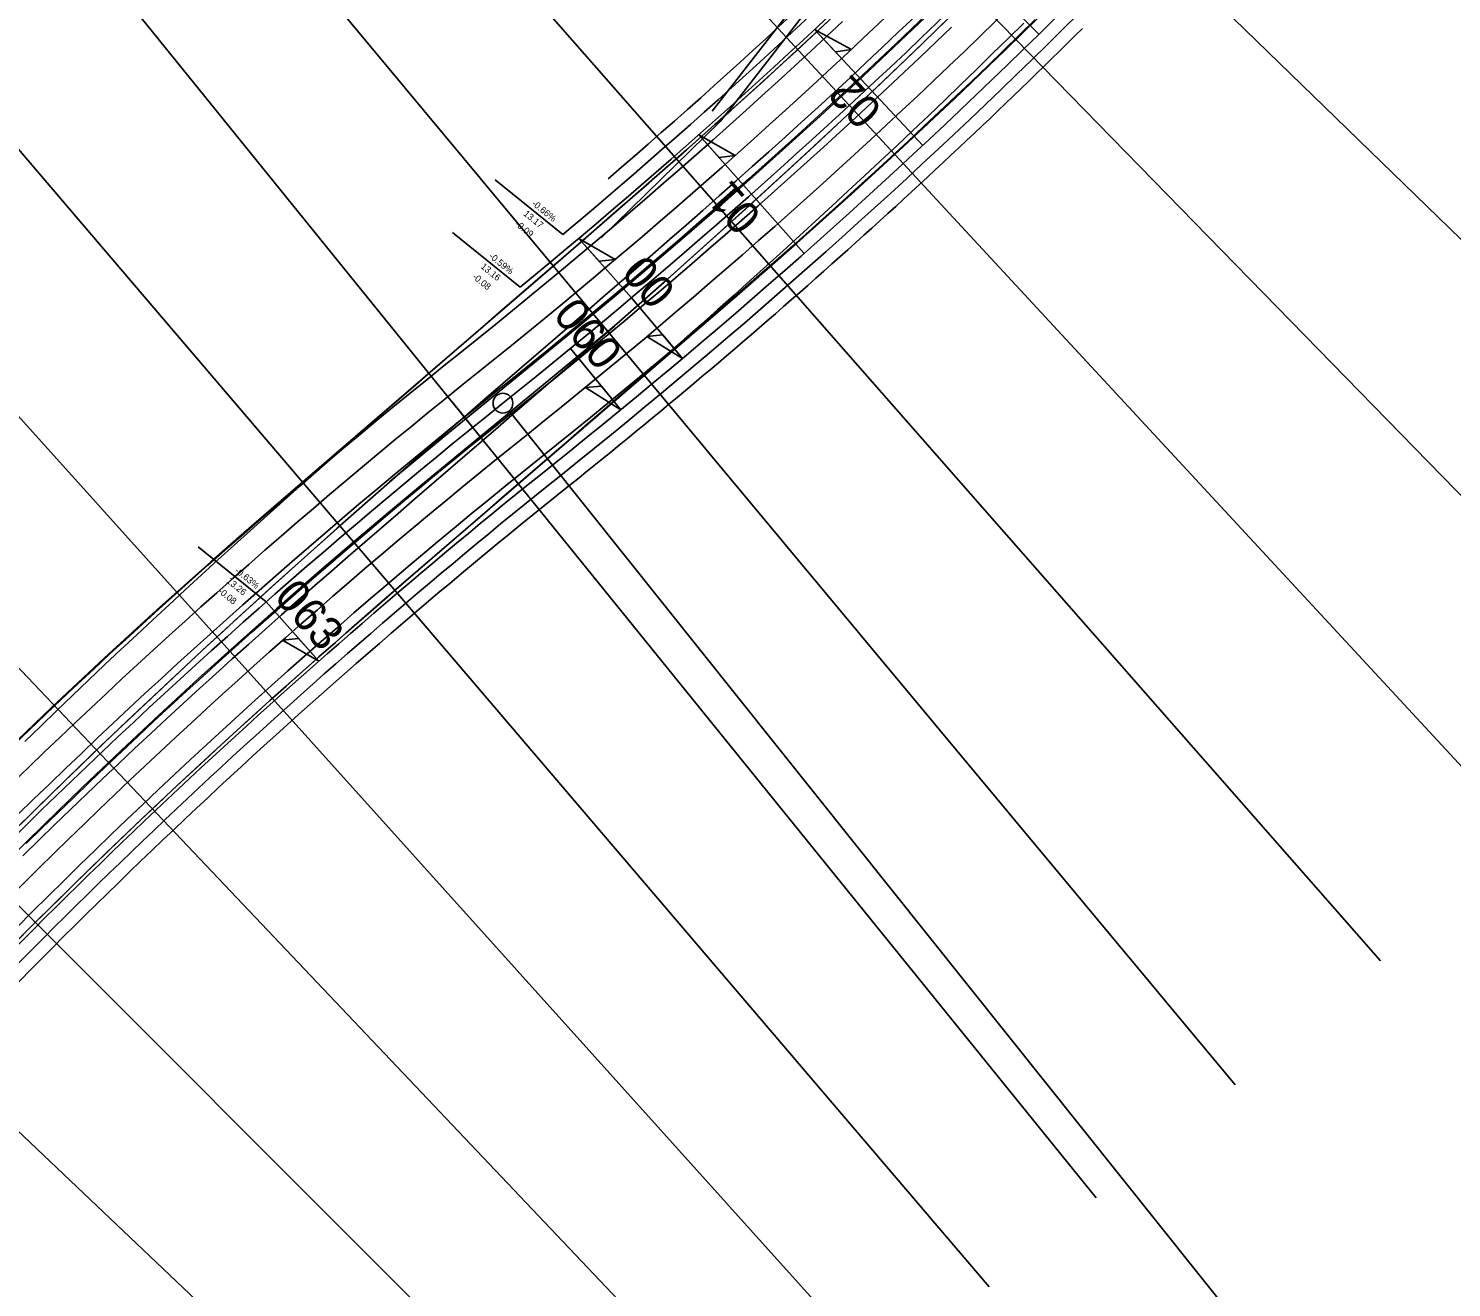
# Model space of a CAD drawing. Extents: x 2293233 to 2294507, y 892788 to 894229.
# Drawn here: x 2293544.7 to 2293760.1, y 893049.3 to 893239.9 of the extents above; entities that cross this region are included whole.
import ezdxf

# ---------------------------------------------------------------- set-up
doc = ezdxf.new("R2010")
doc.units = 0
for name, color, linetype in [('COGO Default Curve', 7, 'Continuous'), ('Default', 7, 'Continuous'), ('Prop EOT', 7, 'Continuous'), ('Prop Horizontal Alignment', 7, 'Continuous'), ('Prop Paved Shoulder', 7, 'Continuous'), ('Prop Superelevation  Arrow CELL', 7, 'Continuous'), ('Prop Superelevation Label', 7, 'Continuous'), ('Scratch_Level_0', 7, 'Continuous'), ('Scratch_Level_4', 7, 'Continuous'), ('Scratch_Level_5', 7, 'Continuous'), ('Scratch_Level_6', 7, 'Continuous')]:
    doc.layers.add(name, color=color, linetype=linetype)

msp = doc.modelspace()

# ---------------------------------------------------------------- linework, layer by layer
at = {"layer": 'COGO Default Curve'}
for points in [[(2293540.51, 893129.71), (2293548.21, 893137.09), (2293556.25, 893144.61), (2293564.12, 893151.82), (2293572.32, 893159.16), (2293576.58, 893162.91), (2293581.11, 893166.85), (2293623.72, 893203.59), (2293633.79, 893212.3), (2293644.32, 893221.52), (2293653.27, 893229.52), (2293658.2, 893234.01), (2293663.1, 893238.53), (2293667.97, 893243.08)], [(2293683.19, 893244.24), (2293678.63, 893239.85), (2293673.79, 893235.26), (2293669.17, 893230.93), (2293664.52, 893226.64), (2293659.84, 893222.37), (2293654.88, 893217.92), (2293649.64, 893213.27), (2293644.36, 893208.67), (2293639.05, 893204.11), (2293633.96, 893199.79), (2293626.26, 893193.39), (2293607.66, 893178.13), (2293599.45, 893171.3), (2293593.21, 893165.79), (2293587.49, 893160.7), (2293581.8, 893155.58), (2293576.38, 893150.65), (2293570.99, 893145.69), (2293565.87, 893140.92), (2293560.78, 893136.12), (2293555.72, 893131.29), (2293550.68, 893126.43), (2293545.92, 893121.77), (2293541.18, 893117.08)], [(2293541.47, 893113.86), (2293547.17, 893119.47), (2293552.91, 893125.04), (2293558.71, 893130.55), (2293564.55, 893136.01), (2293570.43, 893141.43), (2293576.36, 893146.79), (2293582.34, 893152.11), (2293588.37, 893157.38), (2293594.44, 893162.59), (2293599.53, 893166.9), (2293604.66, 893171.18), (2293623.51, 893186.65), (2293632.76, 893194.33), (2293633.78, 893195.19), (2293641.01, 893201.57), (2293647.96, 893207.78), (2293654.87, 893214.04), (2293661.49, 893220.12), (2293667.83, 893226.02), (2293674.13, 893231.97), (2293680.14, 893237.74), (2293686.34, 893243.78)], [(2293697.59, 893241.55), (2293692.58, 893236.66), (2293684.87, 893229.27), (2293677.09, 893221.97), (2293669.22, 893214.76), (2293661.01, 893207.41), (2293656.51, 893203.45), (2293651.97, 893199.5), (2293609.11, 893162.55), (2293598.54, 893153.4), (2293592.76, 893148.36), (2293587.51, 893143.73), (2293582.78, 893139.51), (2293578.08, 893135.27), (2293572.67, 893130.32), (2293567.29, 893125.33), (2293561.96, 893120.3), (2293556.42, 893114.99), (2293551.16, 893109.88), (2293545.7, 893104.49), (2293540.52, 893099.3)], [(2293667.93, 893240.97), (2293665.51, 893238.7), (2293663.08, 893236.44), (2293660.64, 893234.19), (2293658.2, 893231.94), (2293655.74, 893229.7), (2293653.28, 893227.48), (2293650.81, 893225.26), (2293648.33, 893223.05), (2293645.85, 893220.84), (2293643.36, 893218.65), (2293640.85, 893216.47), (2293638.35, 893214.29), (2293635.83, 893212.12), (2293633.31, 893209.97), (2293630.77, 893207.82), (2293628.24, 893205.68), (2293625.69, 893203.55), (2293623.13, 893201.43), (2293620.57, 893199.31), (2293618, 893197.21), (2293615.43, 893195.11), (2293612.84, 893193.03), (2293610.25, 893190.95), (2293607.66, 893188.87), (2293605.06, 893186.78), (2293602.48, 893184.68), (2293599.9, 893182.57), (2293597.32, 893180.44), (2293594.76, 893178.31), (2293592.19, 893176.17), (2293589.64, 893174.02), (2293587.09, 893171.86), (2293584.55, 893169.68), (2293582.02, 893167.5), (2293579.49, 893165.31), (2293576.97, 893163.12), (2293574.46, 893160.91), (2293571.95, 893158.69), (2293569.45, 893156.47), (2293566.96, 893154.23), (2293564.48, 893151.99), (2293562.01, 893149.74), (2293559.54, 893147.48), (2293557.08, 893145.21), (2293554.63, 893142.93), (2293552.19, 893140.64), (2293549.75, 893138.35), (2293547.32, 893136.05), (2293544.9, 893133.73), (2293542.49, 893131.41)], [(2293542.82, 893101.61), (2293545.16, 893103.96), (2293547.52, 893106.29), (2293549.88, 893108.62), (2293552.24, 893110.94), (2293554.62, 893113.25), (2293557, 893115.56), (2293559.39, 893117.85), (2293561.79, 893120.14), (2293564.2, 893122.42), (2293566.61, 893124.69), (2293569.04, 893126.96), (2293571.47, 893129.21), (2293573.9, 893131.46), (2293576.35, 893133.7), (2293578.8, 893135.92), (2293581.26, 893138.15), (2293583.73, 893140.36), (2293586.21, 893142.57), (2293588.7, 893144.77), (2293591.19, 893146.97), (2293593.68, 893149.16), (2293596.19, 893151.35), (2293598.69, 893153.53), (2293601.21, 893155.72), (2293603.72, 893157.9), (2293606.24, 893160.07), (2293608.76, 893162.25), (2293611.28, 893164.43), (2293613.81, 893166.6), (2293616.33, 893168.78), (2293618.86, 893170.96), (2293621.38, 893173.14), (2293623.91, 893175.32), (2293626.43, 893177.5), (2293628.95, 893179.69), (2293631.47, 893181.88), (2293633.99, 893184.07), (2293636.5, 893186.27), (2293639.01, 893188.47), (2293641.52, 893190.67), (2293644.02, 893192.88), (2293646.52, 893195.1), (2293649.02, 893197.32), (2293651.51, 893199.55), (2293653.99, 893201.78), (2293656.48, 893204.02), (2293658.95, 893206.26), (2293661.42, 893208.51), (2293663.89, 893210.77), (2293666.35, 893213.03), (2293668.8, 893215.3), (2293671.25, 893217.58), (2293673.69, 893219.86), (2293676.12, 893222.15), (2293678.55, 893224.45), (2293680.97, 893226.75), (2293683.39, 893229.06), (2293685.79, 893231.38), (2293688.2, 893233.71), (2293690.59, 893236.04), (2293692.98, 893238.38), (2293695.36, 893240.73)], [(2293543.03, 893103.87), (2293545.38, 893106.22), (2293547.73, 893108.56), (2293550.09, 893110.89), (2293552.46, 893113.22), (2293554.84, 893115.53), (2293557.23, 893117.84), (2293559.62, 893120.14), (2293562.03, 893122.43), (2293564.44, 893124.71), (2293566.86, 893126.99), (2293569.28, 893129.25), (2293571.72, 893131.51), (2293574.16, 893133.75), (2293576.61, 893135.99), (2293579.07, 893138.22), (2293581.54, 893140.44), (2293584.01, 893142.66), (2293586.5, 893144.86), (2293588.99, 893147.06), (2293591.49, 893149.24), (2293593.99, 893151.42), (2293596.5, 893153.59), (2293599.03, 893155.75), (2293601.55, 893157.9), (2293604.09, 893160.04), (2293606.63, 893162.18), (2293609.19, 893164.3), (2293611.74, 893166.41), (2293614.31, 893168.52), (2293616.88, 893170.62), (2293619.47, 893172.7), (2293622.05, 893174.78), (2293624.65, 893176.86), (2293627.24, 893178.95), (2293629.83, 893181.05), (2293632.41, 893183.16), (2293634.99, 893185.28), (2293637.56, 893187.41), (2293640.13, 893189.55), (2293642.68, 893191.7), (2293645.24, 893193.86), (2293647.78, 893196.03), (2293650.32, 893198.21), (2293652.85, 893200.39), (2293655.37, 893202.59), (2293657.89, 893204.8), (2293660.39, 893207.01), (2293662.89, 893209.23), (2293665.39, 893211.47), (2293667.87, 893213.71), (2293670.35, 893215.96), (2293672.82, 893218.21), (2293675.28, 893220.48), (2293677.74, 893222.76), (2293680.18, 893225.04), (2293682.62, 893227.34), (2293685.05, 893229.64), (2293687.47, 893231.95), (2293689.89, 893234.27), (2293692.29, 893236.59), (2293694.69, 893238.93), (2293697.08, 893241.27)], [(2293678.85, 893241.67), (2293676.42, 893239.37), (2293673.99, 893237.07), (2293671.55, 893234.78), (2293669.11, 893232.5), (2293666.65, 893230.23), (2293664.19, 893227.96), (2293661.72, 893225.71), (2293659.25, 893223.46), (2293656.76, 893221.23), (2293654.27, 893219), (2293651.77, 893216.77), (2293649.27, 893214.56), (2293646.77, 893212.35), (2293644.25, 893210.15), (2293641.74, 893207.95), (2293639.22, 893205.76), (2293636.7, 893203.57), (2293634.18, 893201.39), (2293631.65, 893199.21), (2293629.13, 893197.03), (2293626.6, 893194.85), (2293624.08, 893192.68), (2293621.56, 893190.5), (2293619.04, 893188.32), (2293616.52, 893186.15), (2293614, 893183.97), (2293611.48, 893181.79), (2293608.97, 893179.61), (2293606.46, 893177.43), (2293603.95, 893175.24), (2293601.45, 893173.05), (2293598.95, 893170.86), (2293596.46, 893168.67), (2293593.97, 893166.46), (2293591.48, 893164.26), (2293589, 893162.05), (2293586.53, 893159.83), (2293584.06, 893157.61), (2293581.59, 893155.39), (2293579.14, 893153.16), (2293576.68, 893150.92), (2293574.24, 893148.68), (2293571.8, 893146.43), (2293569.36, 893144.17), (2293566.93, 893141.91), (2293564.51, 893139.64), (2293562.1, 893137.37), (2293559.69, 893135.09), (2293557.29, 893132.8), (2293554.9, 893130.5), (2293552.51, 893128.2), (2293550.13, 893125.89), (2293547.76, 893123.57), (2293545.39, 893121.25), (2293543.04, 893118.92)], [(2293680.79, 893242.16), (2293678.37, 893239.85), (2293675.94, 893237.54), (2293673.51, 893235.24), (2293671.07, 893232.95), (2293668.62, 893230.66), (2293666.16, 893228.39), (2293663.69, 893226.13), (2293661.22, 893223.87), (2293658.73, 893221.62), (2293656.24, 893219.38), (2293653.74, 893217.15), (2293651.24, 893214.93), (2293648.72, 893212.72), (2293646.2, 893210.52), (2293643.67, 893208.32), (2293641.14, 893206.14), (2293638.59, 893203.96), (2293636.04, 893201.79), (2293633.48, 893199.64), (2293630.91, 893197.49), (2293628.33, 893195.35), (2293625.75, 893193.22), (2293623.16, 893191.09), (2293620.56, 893188.98), (2293617.96, 893186.88), (2293615.34, 893184.78), (2293612.74, 893182.69), (2293610.14, 893180.6), (2293607.56, 893178.5), (2293604.98, 893176.39), (2293602.41, 893174.27), (2293599.85, 893172.14), (2293597.3, 893170.01), (2293594.76, 893167.87), (2293592.22, 893165.72), (2293589.7, 893163.56), (2293587.18, 893161.39), (2293584.67, 893159.22), (2293582.16, 893157.03), (2293579.67, 893154.84), (2293577.18, 893152.64), (2293574.7, 893150.43), (2293572.23, 893148.21), (2293569.77, 893145.99), (2293567.31, 893143.75), (2293564.87, 893141.51), (2293562.43, 893139.26), (2293560, 893137), (2293557.57, 893134.73), (2293555.16, 893132.45), (2293552.75, 893130.17), (2293550.35, 893127.88), (2293547.96, 893125.57), (2293545.58, 893123.26), (2293543.2, 893120.95)], [(2293543.92, 893114.68), (2293546.3, 893117.02), (2293548.7, 893119.35), (2293551.1, 893121.68), (2293553.52, 893123.99), (2293555.94, 893126.3), (2293558.36, 893128.6), (2293560.8, 893130.89), (2293563.24, 893133.18), (2293565.69, 893135.45), (2293568.15, 893137.72), (2293570.62, 893139.97), (2293573.1, 893142.22), (2293575.58, 893144.46), (2293578.07, 893146.7), (2293580.56, 893148.92), (2293583.06, 893151.14), (2293585.57, 893153.35), (2293588.08, 893155.56), (2293590.6, 893157.75), (2293593.11, 893159.95), (2293595.64, 893162.14), (2293598.16, 893164.32), (2293600.68, 893166.5), (2293603.21, 893168.68), (2293605.73, 893170.86), (2293608.26, 893173.04), (2293610.78, 893175.22), (2293613.31, 893177.39), (2293615.83, 893179.57), (2293618.35, 893181.75), (2293620.86, 893183.92), (2293623.38, 893186.11), (2293625.89, 893188.29), (2293628.4, 893190.47), (2293630.9, 893192.66), (2293633.4, 893194.86), (2293635.9, 893197.05), (2293638.39, 893199.25), (2293640.88, 893201.46), (2293643.36, 893203.66), (2293645.84, 893205.88), (2293648.31, 893208.1), (2293650.78, 893210.32), (2293653.24, 893212.55), (2293655.69, 893214.79), (2293658.14, 893217.03), (2293660.58, 893219.28), (2293663.02, 893221.53), (2293665.45, 893223.79), (2293667.87, 893226.06), (2293670.29, 893228.33), (2293672.7, 893230.61), (2293675.1, 893232.9), (2293677.5, 893235.2), (2293679.89, 893237.5), (2293682.27, 893239.81), (2293684.65, 893242.12)], [(2293665.75, 893240.99), (2293663.32, 893238.73), (2293660.89, 893236.47), (2293658.45, 893234.23), (2293656, 893231.99), (2293653.54, 893229.77), (2293651.08, 893227.55), (2293648.61, 893225.34), (2293646.13, 893223.13), (2293643.65, 893220.93), (2293641.15, 893218.74), (2293638.66, 893216.54), (2293636.15, 893214.36), (2293633.64, 893212.18), (2293631.13, 893210), (2293628.62, 893207.82), (2293626.1, 893205.64), (2293623.58, 893203.46), (2293621.05, 893201.29), (2293618.53, 893199.11), (2293616.01, 893196.94), (2293613.48, 893194.76), (2293610.96, 893192.58), (2293608.44, 893190.4), (2293605.91, 893188.22), (2293603.39, 893186.03), (2293600.88, 893183.84), (2293598.36, 893181.65), (2293595.85, 893179.45), (2293593.34, 893177.25), (2293590.83, 893175.04), (2293588.33, 893172.83), (2293585.83, 893170.61), (2293583.34, 893168.39), (2293580.85, 893166.16), (2293578.37, 893163.93), (2293575.89, 893161.69), (2293573.42, 893159.45), (2293570.95, 893157.19), (2293568.48, 893154.94), (2293566.03, 893152.67), (2293563.58, 893150.4), (2293561.13, 893148.12), (2293558.69, 893145.84), (2293556.26, 893143.55), (2293553.84, 893141.25), (2293551.42, 893138.94), (2293549.01, 893136.63), (2293546.6, 893134.31), (2293544.2, 893131.98)], [(2293544.39, 893116.51), (2293546.78, 893118.85), (2293549.18, 893121.19), (2293551.59, 893123.51), (2293554, 893125.83), (2293556.42, 893128.14), (2293558.86, 893130.44), (2293561.3, 893132.74), (2293563.74, 893135.02), (2293566.2, 893137.3), (2293568.66, 893139.56), (2293571.13, 893141.82), (2293573.61, 893144.07), (2293576.1, 893146.31), (2293578.6, 893148.54), (2293581.1, 893150.77), (2293583.61, 893152.98), (2293586.13, 893155.19), (2293588.66, 893157.38), (2293591.19, 893159.57), (2293593.73, 893161.75), (2293596.28, 893163.92), (2293598.84, 893166.08), (2293601.41, 893168.23), (2293603.98, 893170.37), (2293606.56, 893172.51), (2293609.15, 893174.63), (2293611.74, 893176.75), (2293614.35, 893178.85), (2293616.96, 893180.95), (2293619.57, 893183.04), (2293622.16, 893185.13), (2293624.75, 893187.23), (2293627.34, 893189.34), (2293629.91, 893191.46), (2293632.47, 893193.58), (2293635.02, 893195.71), (2293637.57, 893197.85), (2293640.11, 893200), (2293642.64, 893202.16), (2293645.16, 893204.32), (2293647.67, 893206.5), (2293650.18, 893208.68), (2293652.68, 893210.87), (2293655.17, 893213.07), (2293657.65, 893215.27), (2293660.12, 893217.49), (2293662.59, 893219.71), (2293665.05, 893221.95), (2293667.5, 893224.19), (2293669.94, 893226.44), (2293672.37, 893228.7), (2293674.8, 893230.96), (2293677.22, 893233.24), (2293679.63, 893235.52), (2293682.03, 893237.81), (2293684.43, 893240.11)]]:
    msp.add_lwpolyline(points, dxfattribs=at)
msp.add_circle((2293612.8, 893187.87), 0.0417, dxfattribs=at)
msp.add_circle((2293612.8, 893187.87), 0.0417, dxfattribs=at)
for centre, radius, start, end in [((2293023.75, 893925.54), 944, 308.6085, 321.09608), ((2293023.75, 893925.54), 956, 308.6085, 321.09608), ((2294209.34, 892440.82), 956, 128.6085, 141.01247), ((2294209.34, 892440.82), 944, 128.6085, 141.01247)]:
    msp.add_arc(centre, radius, start, end, dxfattribs=at)
at = {"layer": 'Default'}
for p, q in [((2293615.39, 893217), (2293625.63, 893208.71)), ((2293608.92, 893209.01), (2293619.15, 893200.73)), ((2293570.42, 893161.44), (2293580.72, 893153.1))]:
    msp.add_line(p, q, dxfattribs=at)
at = {"layer": 'Prop EOT'}
for centre, radius, start, end in [((2293023.75, 893925.54), 938, 309.40221, 321.09608), ((2293023.75, 893925.54), 962, 308.6085, 321.09608), ((2294209.34, 892440.82), 938, 128.6085, 137.75907)]:
    msp.add_arc(centre, radius, start, end, dxfattribs=at)
at = {"layer": 'Prop Horizontal Alignment'}
for p, q in [((2293611.98, 893179.52), (2293608.84, 893183.4)), ((2293617.48, 893182.01), (2293788.14, 892968.29))]:
    msp.add_line(p, q, dxfattribs=at)
msp.add_circle((2293616.54, 893183.18), 1.5, dxfattribs=at)
for centre, start, end in [((2293023.75, 893925.54), 308.6085, 321.09608), ((2293023.75, 893925.54), 308.6085, 321.09608), ((2294209.34, 892440.82), 128.6085, 141.01247), ((2294209.34, 892440.82), 128.6085, 141.01247)]:
    msp.add_arc(centre, 950, start, end, dxfattribs=at)
at = {"layer": 'Prop Paved Shoulder'}
for centre, radius, start, end in [((2293023.75, 893925.54), 936, 310.01837, 321.09608), ((2293023.75, 893925.54), 964, 308.6085, 321.09608), ((2294209.34, 892440.82), 936, 128.6085, 137.75907)]:
    msp.add_arc(centre, radius, start, end, dxfattribs=at)
at = {"layer": 'Prop Superelevation  Arrow CELL'}
for p, q in [((2293680.83, 893256.14), (2293697.64, 893239.02)), ((2293663.71, 893239.76), (2293680.09, 893222.21)), ((2293646.18, 893223.81), (2293662.11, 893205.86)), ((2293628.03, 893208.11), (2293635.99, 893199.14)), ((2293643.73, 893189.96), (2293635.99, 893199.14)), ((2293634.39, 893182.19), (2293626.77, 893191.46)), ((2293588.66, 893144.1), (2293580.72, 893153.1))]:
    msp.add_line(p, q, dxfattribs=at)
for points in [[(2293663.71, 893239.76), (2293669.27, 893236.74), (2293666.87, 893236.38)], [(2293646.18, 893223.81), (2293651.66, 893220.65), (2293649.25, 893220.35)], [(2293628.03, 893208.11), (2293633.51, 893204.95), (2293631.1, 893204.66)], [(2293643.73, 893189.96), (2293638.33, 893193.26), (2293640.75, 893193.5)], [(2293634.39, 893182.19), (2293629.03, 893185.56), (2293631.45, 893185.76)], [(2293588.66, 893144.1), (2293583.19, 893147.28), (2293585.6, 893147.57)]]:
    msp.add_lwpolyline(points, close=True, dxfattribs=at)
at = {"layer": 'Scratch_Level_0'}
for p, q in [((2293678.41, 893263.12), (2293651.3, 893228.13)), ((2293649.42, 893225.8), (2293651.3, 893228.13)), ((2293631.42, 893208.2), (2293649.42, 893225.8))]:
    msp.add_line(p, q, dxfattribs=at)
at = {"layer": 'Scratch_Level_4'}
for p, q in [((2293597.22, 893367.75), (2293812.28, 893158.58)), ((2293582.35, 893352.85), (2293791.82, 893138.1)), ((2293567.08, 893338.35), (2293770.84, 893118.16)), ((2293551.45, 893324.26), (2293749.33, 893098.78)), ((2293535.44, 893310.58), (2293727.33, 893079.98)), ((2293517.66, 893296.15), (2293706.3, 893062.88)), ((2293495.4, 893277.65), (2293690.11, 893049.43)), ((2293473.62, 893258.58), (2293674.27, 893035.55)), ((2293452.36, 893238.94), (2293658.81, 893021.27)), ((2293431.62, 893218.74), (2293643.73, 893006.58)), ((2293411.42, 893198.01), (2293629.04, 892991.5))]:
    msp.add_line(p, q, dxfattribs=at)
at = {"layer": 'Scratch_Level_5'}
msp.add_line((2293648.21, 893227.37), (2293676.84, 893264.33), dxfattribs=at)
for centre, radius, start, end in [((2293023.75, 893925.54), 934, 310.67386, 321.09608), ((2293023.75, 893925.54), 966, 308.6085, 314.78443), ((2294209.34, 892440.82), 934, 128.6085, 137.75907)]:
    msp.add_arc(centre, radius, start, end, dxfattribs=at)
at = {"layer": 'Scratch_Level_6'}
for p, q in [((2293615.39, 893217), (2293625.63, 893208.71)), ((2293608.92, 893209.01), (2293619.15, 893200.73)), ((2293570.42, 893161.44), (2293580.72, 893153.1))]:
    msp.add_line(p, q, dxfattribs=at)

# ---------------------------------------------------------------- texts
at = {"layer": 'Default'}
for s, p in [('-0.66%', (2293620.82, 893213.24)), ('-0.09', (2293618.3, 893210.13)), ('13.17', (2293619.56, 893211.69)), ('13.16', (2293613.09, 893203.71)), ('-0.59%', (2293614.35, 893205.26)), ('-0.08', (2293611.84, 893202.15)), ('13.26', (2293574.63, 893156.11)), ('-0.63%', (2293575.89, 893157.66)), ('-0.08', (2293573.37, 893154.55))]:
    msp.add_text(s, height=1, rotation=321.0125, dxfattribs=at).set_placement(p)
at = {"layer": 'Prop Superelevation Label'}
for s, rotation, p in [('02', 133.0209, (2293674.16, 893227.73)), ('01', 131.5735, (2293655.89, 893211.58)), ('00', 310.126, (2293634.29, 893202.76)), ('060', 309.4022, (2293623.97, 893196.44)), ('063', 311.4298, (2293581.75, 893153.73))]:
    msp.add_text(s, height=5, rotation=rotation, dxfattribs=at).set_placement(p)

doc.saveas('drawing.dxf')
